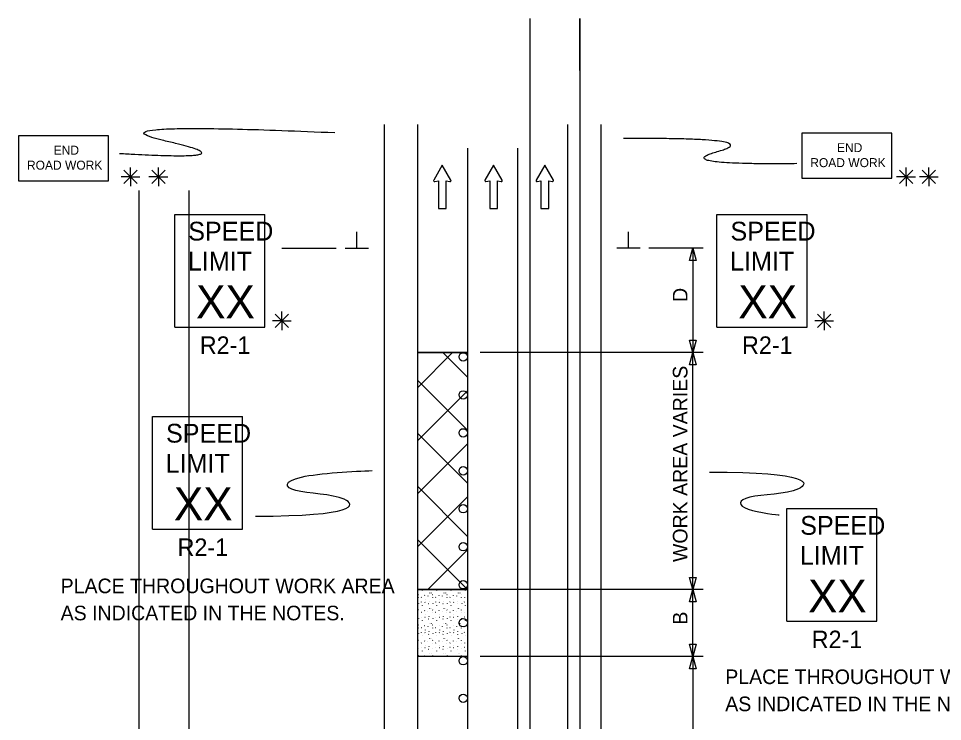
# Model space of a CAD drawing. Extents: x 16576 to 19508, y 5728 to 6974.
# Drawn here: x 16735.5 to 17178.6, y 6637 to 6974.1 of the extents above; entities that cross this region are included whole.
import ezdxf

# ---------------------------------------------------------------- set-up
doc = ezdxf.new("R2010")
doc.units = 0
for name, color, linetype in [('ALI_LEGAL_EX', 7, 'Continuous'), ('MT_SCRATCH_LEVEL_E', 7, 'Continuous'), ('PAVT_EDGE_EX', 7, 'Continuous'), ('TRAFFIC_SIGNS_PR', 7, 'Continuous'), ('TYPICAL_TEXT_DIMEN_PR', 7, 'Continuous')]:
    doc.layers.add(name, color=color, linetype=linetype)

msp = doc.modelspace()

# ---------------------------------------------------------------- linework, layer by layer
at = {"layer": 'ALI_LEGAL_EX'}
for p, q in [((16980.68, 6974.12), (16980.68, 6155.98)), ((17004.68, 6974.12), (17004.68, 6155.98)), ((16950.77, 6911.88), (16950.77, 6082.69)), ((16974.77, 6911.88), (16974.77, 6082.69)), ((16793.2, 6891.57), (16793.2, 6027.66)), ((16817.2, 6891.57), (16817.2, 6027.66))]:
    msp.add_line(p, q, dxfattribs=at)
for points in [[(17004.68, 6949.12), (17004.68, 6974.12)], [(16950.77, 6911.88), (16950.77, 6886.88)], [(16974.77, 6911.88), (16974.77, 6886.88)], [(16950.77, 6811.88), (16950.77, 6786.88)], [(16974.77, 6811.88), (16974.77, 6786.88)], [(16950.77, 6711.88), (16950.77, 6686.88)], [(16974.77, 6711.88), (16974.77, 6686.88)]]:
    msp.add_lwpolyline(points, dxfattribs=at)
at = {"layer": 'MT_SCRATCH_LEVEL_E'}
for p, q in [((16938.74, 6903.85), (16934.63, 6896.61)), ((16942.89, 6896.61), (16938.74, 6903.85)), ((16963.3, 6903.85), (16959.19, 6896.61)), ((16967.44, 6896.61), (16963.3, 6903.85)), ((16987.86, 6903.85), (16983.75, 6896.61)), ((16992, 6896.61), (16987.86, 6903.85)), ((16935.11, 6895.92), (16936.89, 6896.24)), ((16936.89, 6896.24), (16936.89, 6882.98)), ((16940.63, 6882.98), (16940.63, 6896.24)), ((16940.63, 6896.24), (16942.41, 6895.92)), ((16959.67, 6895.92), (16961.45, 6896.24)), ((16961.45, 6896.24), (16961.45, 6882.98)), ((16965.19, 6882.98), (16965.19, 6896.24)), ((16965.19, 6896.24), (16966.97, 6895.92)), ((16984.23, 6895.92), (16986.01, 6896.24)), ((16986.01, 6896.24), (16986.01, 6882.98)), ((16989.75, 6882.98), (16989.75, 6896.24)), ((16989.75, 6896.24), (16991.53, 6895.92)), ((16936.89, 6882.98), (16940.63, 6882.98)), ((16961.45, 6882.98), (16965.19, 6882.98)), ((16986.01, 6882.98), (16989.75, 6882.98))]:
    msp.add_line(p, q, dxfattribs=at)
for centre, start, end in [((16935.04, 6896.38), 150.4248, 279.9638), ((16942.48, 6896.38), 260.0362, 29.7731), ((16959.59, 6896.38), 150.4248, 279.9638), ((16967.04, 6896.38), 260.0362, 29.7731), ((16984.15, 6896.38), 150.4248, 279.9638), ((16991.59, 6896.38), 260.0362, 29.7731)]:
    msp.add_arc(centre, 0.463, start, end, dxfattribs=at)
at = {"layer": 'PAVT_EDGE_EX'}
for p, q in [((16910.77, 6923.28), (16910.77, 5986.88)), ((16926.77, 6923.28), (16926.77, 5986.88)), ((16998.77, 6923.28), (16998.77, 5986.88)), ((17014.77, 6923.28), (17014.77, 5986.88)), ((16926.77, 6813.97), (16950.77, 6813.97)), ((16926.77, 6797.07), (16943.67, 6813.97)), ((16950.86, 6813.97), (16926.86, 6813.97)), ((16950.77, 6802.15), (16938.96, 6813.97)), ((16950.77, 6776.7), (16926.77, 6800.7)), ((16926.77, 6771.61), (16950.77, 6795.61)), ((16950.77, 6751.24), (16926.77, 6775.24)), ((16926.77, 6746.16), (16950.77, 6770.16)), ((16950.77, 6725.79), (16926.77, 6749.79)), ((16926.77, 6720.7), (16950.77, 6744.7)), ((16950.77, 6700.33), (16926.77, 6724.33)), ((16931.77, 6700.24), (16950.86, 6719.34)), ((16950.77, 6700.24), (16926.77, 6700.24)), ((16950.86, 6700.24), (16926.86, 6700.24)), ((16926.86, 6700.24), (16950.86, 6700.24)), ((16927.17, 6696.42), (16927.12, 6696.34)), ((16927.25, 6697.69), (16927.2, 6697.81)), ((16928.7, 6696.56), (16928.65, 6696.48)), ((16929.27, 6699.89), (16929.22, 6700)), ((16930.32, 6697.39), (16930.27, 6697.51)), ((16931.77, 6697.24), (16931.72, 6697.16)), ((16932.64, 6698.62), (16932.58, 6698.54)), ((16933.37, 6698.65), (16933.32, 6698.57)), ((16934.06, 6696.42), (16934.01, 6696.34)), ((16934.14, 6697.69), (16934.08, 6697.81)), ((16935.59, 6696.56), (16935.53, 6696.48)), ((16936.16, 6699.89), (16936.1, 6700)), ((16937.21, 6697.39), (16937.15, 6697.51)), ((16938.65, 6697.24), (16938.6, 6697.16)), ((16939.52, 6698.62), (16939.47, 6698.54)), ((16940.26, 6698.65), (16940.21, 6698.57)), ((16940.94, 6696.42), (16940.89, 6696.34)), ((16941.02, 6697.69), (16940.97, 6697.81)), ((16942.47, 6696.56), (16942.42, 6696.48)), ((16943.04, 6699.89), (16942.99, 6700)), ((16944.09, 6697.39), (16944.04, 6697.51)), ((16945.54, 6697.24), (16945.49, 6697.16)), ((16946.41, 6698.62), (16946.36, 6698.54)), ((16947.15, 6698.65), (16947.1, 6698.57)), ((16947.83, 6696.42), (16947.78, 6696.34)), ((16947.91, 6697.69), (16947.86, 6697.81)), ((16949.36, 6696.56), (16949.31, 6696.48)), ((16949.93, 6699.89), (16949.88, 6700)), ((16950.86, 6700.24), (16950.86, 6700.24)), ((16927.37, 6693.78), (16927.36, 6693.66)), ((16928.65, 6694.35), (16928.6, 6694.28)), ((16929.27, 6692.6), (16929.22, 6692.72)), ((16930.45, 6694.1), (16930.4, 6694.22)), ((16930.49, 6695.5), (16930.44, 6695.43)), ((16932.23, 6693.43), (16932.17, 6693.36)), ((16932.42, 6694.63), (16932.36, 6694.75)), ((16934.26, 6693.78), (16934.24, 6693.66)), ((16935.54, 6694.35), (16935.49, 6694.28)), ((16936.16, 6692.6), (16936.1, 6692.72)), ((16937.33, 6694.1), (16937.28, 6694.22)), ((16937.38, 6695.5), (16937.33, 6695.43)), ((16939.11, 6693.43), (16939.06, 6693.36)), ((16939.3, 6694.63), (16939.25, 6694.75)), ((16941.14, 6693.78), (16941.13, 6693.66)), ((16942.43, 6694.35), (16942.37, 6694.28)), ((16943.04, 6692.6), (16942.99, 6692.72)), ((16944.22, 6694.1), (16944.17, 6694.22)), ((16944.26, 6695.5), (16944.21, 6695.43)), ((16946, 6693.43), (16945.95, 6693.36)), ((16946.19, 6694.63), (16946.14, 6694.75)), ((16948.03, 6693.78), (16948.02, 6693.66)), ((16949.31, 6694.35), (16949.26, 6694.28)), ((16949.93, 6692.6), (16949.88, 6692.72)), ((16927.17, 6689.14), (16927.12, 6689.06)), ((16927.25, 6690.4), (16927.2, 6690.52)), ((16928.7, 6689.28), (16928.65, 6689.2)), ((16930.32, 6690.11), (16930.27, 6690.22)), ((16930.49, 6688.22), (16930.44, 6688.14)), ((16931.77, 6689.95), (16931.72, 6689.88)), ((16932.42, 6687.35), (16932.36, 6687.46)), ((16932.64, 6691.33), (16932.58, 6691.26)), ((16933.37, 6691.36), (16933.32, 6691.29)), ((16934.06, 6689.14), (16934.01, 6689.06)), ((16934.14, 6690.4), (16934.08, 6690.52)), ((16935.59, 6689.28), (16935.53, 6689.2)), ((16937.21, 6690.11), (16937.15, 6690.22)), ((16937.38, 6688.22), (16937.33, 6688.14)), ((16938.65, 6689.95), (16938.6, 6689.88)), ((16939.3, 6687.35), (16939.25, 6687.46)), ((16939.52, 6691.33), (16939.47, 6691.26)), ((16940.26, 6691.36), (16940.21, 6691.29)), ((16940.94, 6689.14), (16940.89, 6689.06)), ((16941.02, 6690.4), (16940.97, 6690.52)), ((16942.47, 6689.28), (16942.42, 6689.2)), ((16944.09, 6690.11), (16944.04, 6690.22)), ((16944.26, 6688.22), (16944.21, 6688.14)), ((16945.54, 6689.95), (16945.49, 6689.88)), ((16946.19, 6687.35), (16946.14, 6687.46)), ((16946.41, 6691.33), (16946.36, 6691.26)), ((16947.15, 6691.36), (16947.1, 6691.29)), ((16947.83, 6689.14), (16947.78, 6689.06)), ((16947.91, 6690.4), (16947.86, 6690.52)), ((16949.36, 6689.28), (16949.31, 6689.2)), ((16927.25, 6683.12), (16927.2, 6683.24)), ((16927.37, 6686.49), (16927.36, 6686.38)), ((16928.65, 6687.07), (16928.6, 6686.99)), ((16929.27, 6685.32), (16929.22, 6685.43)), ((16930.45, 6686.82), (16930.4, 6686.93)), ((16932.23, 6686.15), (16932.17, 6686.07)), ((16932.64, 6684.05), (16932.58, 6683.97)), ((16933.37, 6684.08), (16933.32, 6684)), ((16934.14, 6683.12), (16934.08, 6683.24)), ((16934.26, 6686.49), (16934.24, 6686.38)), ((16935.54, 6687.07), (16935.49, 6686.99)), ((16936.16, 6685.32), (16936.1, 6685.43)), ((16937.33, 6686.82), (16937.28, 6686.93)), ((16939.11, 6686.15), (16939.06, 6686.07)), ((16939.52, 6684.05), (16939.47, 6683.97)), ((16940.26, 6684.08), (16940.21, 6684)), ((16941.02, 6683.12), (16940.97, 6683.24)), ((16941.14, 6686.49), (16941.13, 6686.38)), ((16942.43, 6687.07), (16942.37, 6686.99)), ((16943.04, 6685.32), (16942.99, 6685.43)), ((16944.22, 6686.82), (16944.17, 6686.93)), ((16946, 6686.15), (16945.95, 6686.07)), ((16946.41, 6684.05), (16946.36, 6683.97)), ((16947.15, 6684.08), (16947.1, 6684)), ((16947.91, 6683.12), (16947.86, 6683.24)), ((16948.03, 6686.49), (16948.02, 6686.38)), ((16949.31, 6687.07), (16949.26, 6686.99)), ((16949.93, 6685.32), (16949.88, 6685.43)), ((16927.17, 6681.85), (16927.12, 6681.77)), ((16927.37, 6679.21), (16927.36, 6679.09)), ((16928.65, 6679.78), (16928.6, 6679.7)), ((16928.7, 6681.99), (16928.65, 6681.91)), ((16930.32, 6682.82), (16930.27, 6682.94)), ((16930.45, 6679.53), (16930.4, 6679.65)), ((16930.49, 6680.93), (16930.44, 6680.86)), ((16931.77, 6682.67), (16931.72, 6682.59)), ((16932.23, 6678.86), (16932.17, 6678.79)), ((16932.42, 6680.06), (16932.36, 6680.18)), ((16934.06, 6681.85), (16934.01, 6681.77)), ((16934.26, 6679.21), (16934.24, 6679.09)), ((16935.54, 6679.78), (16935.49, 6679.7)), ((16935.59, 6681.99), (16935.53, 6681.91)), ((16937.21, 6682.82), (16937.15, 6682.94)), ((16937.33, 6679.53), (16937.28, 6679.65)), ((16937.38, 6680.93), (16937.33, 6680.86)), ((16938.65, 6682.67), (16938.6, 6682.59)), ((16939.11, 6678.86), (16939.06, 6678.79)), ((16939.3, 6680.06), (16939.25, 6680.18)), ((16940.94, 6681.85), (16940.89, 6681.77)), ((16941.14, 6679.21), (16941.13, 6679.09)), ((16942.43, 6679.78), (16942.37, 6679.7)), ((16942.47, 6681.99), (16942.42, 6681.91)), ((16944.09, 6682.82), (16944.04, 6682.94)), ((16944.22, 6679.53), (16944.17, 6679.65)), ((16944.26, 6680.93), (16944.21, 6680.86)), ((16945.54, 6682.67), (16945.49, 6682.59)), ((16946, 6678.86), (16945.95, 6678.79)), ((16946.19, 6680.06), (16946.14, 6680.18)), ((16947.83, 6681.85), (16947.78, 6681.77)), ((16948.03, 6679.21), (16948.02, 6679.09)), ((16949.31, 6679.78), (16949.26, 6679.7)), ((16949.36, 6681.99), (16949.31, 6681.91)), ((16927.17, 6674.57), (16927.12, 6674.49)), ((16927.25, 6675.83), (16927.2, 6675.95)), ((16928.7, 6674.71), (16928.65, 6674.63)), ((16929.27, 6678.03), (16929.22, 6678.15)), ((16930.32, 6675.54), (16930.27, 6675.65)), ((16931.77, 6675.39), (16931.72, 6675.31)), ((16932.64, 6676.76), (16932.58, 6676.69)), ((16933.37, 6676.79), (16933.32, 6676.72)), ((16934.06, 6674.57), (16934.01, 6674.49)), ((16934.14, 6675.83), (16934.08, 6675.95)), ((16935.59, 6674.71), (16935.53, 6674.63)), ((16936.16, 6678.03), (16936.1, 6678.15)), ((16937.21, 6675.54), (16937.15, 6675.65)), ((16938.65, 6675.39), (16938.6, 6675.31)), ((16939.52, 6676.76), (16939.47, 6676.69)), ((16940.26, 6676.79), (16940.21, 6676.72)), ((16940.94, 6674.57), (16940.89, 6674.49)), ((16941.02, 6675.83), (16940.97, 6675.95)), ((16942.47, 6674.71), (16942.42, 6674.63)), ((16943.04, 6678.03), (16942.99, 6678.15)), ((16944.09, 6675.54), (16944.04, 6675.65)), ((16945.54, 6675.39), (16945.49, 6675.31)), ((16946.41, 6676.76), (16946.36, 6676.69)), ((16947.15, 6676.79), (16947.1, 6676.72)), ((16947.83, 6674.57), (16947.78, 6674.49)), ((16947.91, 6675.83), (16947.86, 6675.95)), ((16949.36, 6674.71), (16949.31, 6674.63)), ((16949.93, 6678.03), (16949.88, 6678.15)), ((16927.37, 6671.92), (16927.36, 6671.81)), ((16928.65, 6672.5), (16928.6, 6672.42)), ((16929.27, 6670.74), (16929.22, 6670.86)), ((16930.45, 6672.25), (16930.4, 6672.36)), ((16930.49, 6673.65), (16930.44, 6673.57)), ((16932.23, 6671.58), (16932.17, 6671.5)), ((16932.42, 6672.78), (16932.36, 6672.9)), ((16934.26, 6671.92), (16934.24, 6671.81)), ((16935.54, 6672.5), (16935.49, 6672.42)), ((16936.16, 6670.74), (16936.1, 6670.86)), ((16937.33, 6672.25), (16937.28, 6672.36)), ((16937.38, 6673.65), (16937.33, 6673.57)), ((16939.11, 6671.58), (16939.06, 6671.5)), ((16939.3, 6672.78), (16939.25, 6672.9)), ((16941.14, 6671.92), (16941.13, 6671.81)), ((16942.43, 6672.5), (16942.37, 6672.42)), ((16943.04, 6670.74), (16942.99, 6670.86)), ((16944.22, 6672.25), (16944.17, 6672.36)), ((16944.26, 6673.65), (16944.21, 6673.57)), ((16946, 6671.58), (16945.95, 6671.5)), ((16946.19, 6672.78), (16946.14, 6672.9)), ((16948.03, 6671.92), (16948.02, 6671.81)), ((16949.31, 6672.5), (16949.26, 6672.42)), ((16949.93, 6670.74), (16949.88, 6670.86)), ((16950.77, 6668.18), (16926.77, 6668.18)), ((16950.86, 6668.18), (16926.86, 6668.18)), ((16927.25, 6668.55), (16927.2, 6668.66)), ((16930.32, 6668.25), (16930.27, 6668.37)), ((16932.64, 6669.48), (16932.58, 6669.4)), ((16933.37, 6669.51), (16933.32, 6669.43)), ((16934.14, 6668.55), (16934.08, 6668.66)), ((16937.21, 6668.25), (16937.15, 6668.37)), ((16939.52, 6669.48), (16939.47, 6669.4)), ((16940.26, 6669.51), (16940.21, 6669.43)), ((16941.02, 6668.55), (16940.97, 6668.66)), ((16944.09, 6668.25), (16944.04, 6668.37)), ((16946.41, 6669.48), (16946.36, 6669.4)), ((16947.15, 6669.51), (16947.1, 6669.43)), ((16947.91, 6668.55), (16947.86, 6668.66))]:
    msp.add_line(p, q, dxfattribs=at)
at = {"layer": 'TRAFFIC_SIGNS_PR'}
for p, q in [((16810.4, 6880.17), (16853.6, 6880.17)), ((16810.4, 6826.17), (16810.4, 6880.17)), ((16853.6, 6826.17), (16853.6, 6880.17)), ((17070.45, 6880.17), (17113.65, 6880.17)), ((17070.45, 6826.17), (17070.45, 6880.17)), ((17113.65, 6826.17), (17113.65, 6880.17)), ((16810.4, 6826.17), (16853.6, 6826.17)), ((17070.45, 6826.17), (17113.65, 6826.17)), ((16799.74, 6783.27), (16842.94, 6783.27)), ((16799.74, 6729.27), (16799.74, 6783.27)), ((16842.94, 6729.27), (16842.94, 6783.27)), ((17103.89, 6739.06), (17147.09, 6739.06)), ((17103.89, 6685.06), (17103.89, 6739.06)), ((17147.09, 6685.06), (17147.09, 6739.06)), ((16799.74, 6729.27), (16842.94, 6729.27)), ((17103.89, 6685.06), (17147.09, 6685.06))]:
    msp.add_line(p, q, dxfattribs=at)
for points in [[(16735.46, 6896.3), (16778.66, 6896.3), (16778.66, 6917.9), (16735.46, 6917.9)], [(17111.13, 6897.5), (17154.33, 6897.5), (17154.33, 6919.1), (17111.13, 6919.1)]]:
    msp.add_lwpolyline(points, close=True, dxfattribs=at)
for centre in [(16948.76, 6811.85), (16948.76, 6793.63), (16948.76, 6775.42), (16948.76, 6757.2), (16948.76, 6738.99), (16948.76, 6720.77), (16948.76, 6702.56), (16948.76, 6684.35), (16948.76, 6666.13), (16948.76, 6648.13)]:
    msp.add_circle(centre, 2, dxfattribs=at)
for points in [[(16783.94, 6909.41), (16849.1, 6905.54), (16764.08, 6924.88), (16887.17, 6919.39)], [(17108.72, 6904.51), (17046.96, 6903.75), (17094.87, 6917.06), (17025.7, 6916.51)]]:
    msp.add_open_spline(points, degree=2, dxfattribs=at)
at = {"layer": 'TYPICAL_TEXT_DIMEN_PR'}
for p, q in [((16786.07, 6901.37), (16792.44, 6894.99)), ((16792.44, 6901.37), (16786.07, 6894.99)), ((16789.26, 6898.18), (16789.26, 6902.64)), ((16799.39, 6901.37), (16805.77, 6894.99)), ((16805.77, 6901.37), (16799.39, 6894.99)), ((16802.58, 6898.18), (16802.58, 6902.64)), ((17157.97, 6901.35), (17164.35, 6894.97)), ((17164.35, 6901.35), (17157.97, 6894.97)), ((17161.16, 6898.16), (17161.16, 6902.62)), ((17168.94, 6901.35), (17175.32, 6894.97)), ((17175.32, 6901.35), (17168.94, 6894.97)), ((17172.13, 6898.16), (17172.13, 6902.62)), ((16789.26, 6898.18), (16784.72, 6898.18)), ((16789.26, 6898.18), (16792.44, 6898.18)), ((16789.26, 6898.18), (16793.74, 6898.18)), ((16789.26, 6898.18), (16789.26, 6893.68)), ((16802.58, 6898.18), (16798.05, 6898.18)), ((16802.58, 6898.18), (16805.77, 6898.18)), ((16802.58, 6898.18), (16807.06, 6898.18)), ((16802.58, 6898.18), (16802.58, 6893.68)), ((17161.16, 6898.16), (17156.63, 6898.16)), ((17161.16, 6898.16), (17164.35, 6898.16)), ((17161.16, 6898.16), (17165.64, 6898.16)), ((17161.16, 6898.16), (17161.16, 6893.66)), ((17172.13, 6898.16), (17167.6, 6898.16)), ((17172.13, 6898.16), (17175.32, 6898.16)), ((17172.13, 6898.16), (17176.61, 6898.16)), ((17172.13, 6898.16), (17172.13, 6893.66)), ((16897.73, 6863.97), (16897.73, 6871.75)), ((17027.98, 6863.97), (17027.98, 6871.75)), ((16861.77, 6863.97), (16887.77, 6863.97)), ((16892.11, 6863.97), (16903.36, 6863.97)), ((17033.61, 6863.97), (17022.36, 6863.97)), ((17063.86, 6863.97), (17037.86, 6863.97)), ((17057.29, 6858.11), (17058.86, 6863.97)), ((17058.86, 6863.97), (17058.86, 6813.97)), ((17058.86, 6863.97), (17060.43, 6858.11)), ((17058.86, 6858.11), (17057.29, 6858.11)), ((17060.43, 6858.11), (17058.86, 6858.11)), ((17058.86, 6838.84), (17058.86, 6835.07)), ((16858.61, 6832.39), (16864.99, 6826.01)), ((16864.99, 6832.39), (16858.61, 6826.01)), ((16861.8, 6829.2), (16861.8, 6833.66)), ((17118.72, 6832.39), (17125.09, 6826.01)), ((17125.09, 6832.39), (17118.72, 6826.01)), ((17121.9, 6829.2), (17121.9, 6833.66)), ((16861.8, 6829.2), (16857.27, 6829.2)), ((16861.8, 6829.2), (16864.99, 6829.2)), ((16861.8, 6829.2), (16866.28, 6829.2)), ((16861.8, 6829.2), (16861.8, 6824.7)), ((17121.9, 6829.2), (17117.37, 6829.2)), ((17121.9, 6829.2), (17125.09, 6829.2)), ((17121.9, 6829.2), (17126.38, 6829.2)), ((17121.9, 6829.2), (17121.9, 6824.7)), ((17058.86, 6813.97), (17057.29, 6819.83)), ((17057.29, 6819.83), (17058.86, 6819.83)), ((17058.86, 6819.83), (17060.43, 6819.83)), ((17060.43, 6819.83), (17058.86, 6813.97)), ((17063.86, 6813.97), (16956.85, 6813.97)), ((17057.29, 6808.11), (17058.86, 6813.97)), ((17058.86, 6700.24), (17058.86, 6813.97)), ((17058.86, 6813.97), (17060.43, 6808.11)), ((17058.86, 6808.11), (17057.29, 6808.11)), ((17060.43, 6808.11), (17058.86, 6808.11)), ((17058.86, 6700.24), (17057.29, 6706.11)), ((17057.29, 6706.11), (17058.86, 6706.11)), ((17058.86, 6706.11), (17060.43, 6706.11)), ((17060.43, 6706.11), (17058.86, 6700.24)), ((17063.86, 6700.24), (16956.85, 6700.24)), ((17057.29, 6694.38), (17058.86, 6700.24)), ((17058.86, 6668.18), (17058.86, 6700.24)), ((17058.86, 6700.24), (17060.43, 6694.38)), ((17058.86, 6694.38), (17057.29, 6694.38)), ((17060.43, 6694.38), (17058.86, 6694.38)), ((17058.86, 6668.18), (17057.29, 6674.05)), ((17057.29, 6674.05), (17058.86, 6674.05)), ((17058.86, 6674.05), (17060.43, 6674.05)), ((17060.43, 6674.05), (17058.86, 6668.18)), ((17063.86, 6668.18), (16956.85, 6668.18)), ((17057.29, 6662.32), (17058.86, 6668.18)), ((17058.86, 6668.18), (17058.77, 6576.13)), ((17058.86, 6668.18), (17060.43, 6662.32)), ((17058.86, 6662.32), (17057.29, 6662.32)), ((17060.43, 6662.32), (17058.86, 6662.32))]:
    msp.add_line(p, q, dxfattribs=at)
for points in [[(16849.09, 6735.48), (16897.56, 6735.48), (16897.56, 6746.23), (16862.64, 6746.23), (16862.64, 6755.28), (16896.85, 6757.04), (16905.14, 6757.33)], [(17066.85, 6756.62), (17115.32, 6756.62), (17115.32, 6745.86), (17080.4, 6745.86), (17080.4, 6738.04), (17100.23, 6736.09), (17100.24, 6736.08)]]:
    msp.add_open_spline(points, degree=3, dxfattribs=at)

# ---------------------------------------------------------------- texts
at = {"layer": 'TRAFFIC_SIGNS_PR'}
for s, height, p in [('END', 4.31, (17128.01, 6910.02)), ('END', 4.31, (16752.34, 6908.82)), ('ROAD WORK', 4.31, (16739.52, 6901.63)), ('ROAD WORK', 4.31, (17115.19, 6902.84)), ('SPEED', 9, (16816.89, 6867.64)), ('SPEED', 9, (17076.94, 6867.64)), ('LIMIT', 9, (16816.7, 6853.24)), ('LIMIT', 9, (17076.75, 6853.24)), ('XX', 15.785, (16820.65, 6830.39)), ('XX', 15.785, (17080.7, 6830.39)), ('R2-1', 8.37, (16822.41, 6813.3)), ('R2-1', 8.37, (17082.46, 6813.3)), ('SPEED', 9, (16806.23, 6770.74)), ('LIMIT', 9, (16806.05, 6756.34)), ('XX', 15.785, (16809.99, 6733.49)), ('SPEED', 9, (17110.38, 6726.53)), ('R2-1', 8.37, (16811.75, 6716.4)), ('LIMIT', 9, (17110.2, 6712.13)), ('PLACE THROUGHOUT WORK AREA', 7, (16755.68, 6698.52)), ('XX', 15.785, (17114.15, 6689.29)), ('AS INDICATED IN THE NOTES.', 7, (16755.68, 6685.52)), ('R2-1', 8.37, (17115.9, 6672.19)), ('PLACE THROUGHOUT WORK AREA', 7, (17074.43, 6654.95)), ('AS INDICATED IN THE NOTES.', 7, (17074.43, 6641.95))]:
    msp.add_text(s, height=height, dxfattribs=at).set_placement(p)
at = {"layer": 'TYPICAL_TEXT_DIMEN_PR'}
for s, p in [('D', (17056.3, 6838.19)), ('WORK AREA VARIES', (17056.3, 6713.46)), ('B', (17056.3, 6683.45))]:
    msp.add_text(s, height=7, rotation=90, dxfattribs=at).set_placement(p)

doc.saveas('drawing.dxf')
